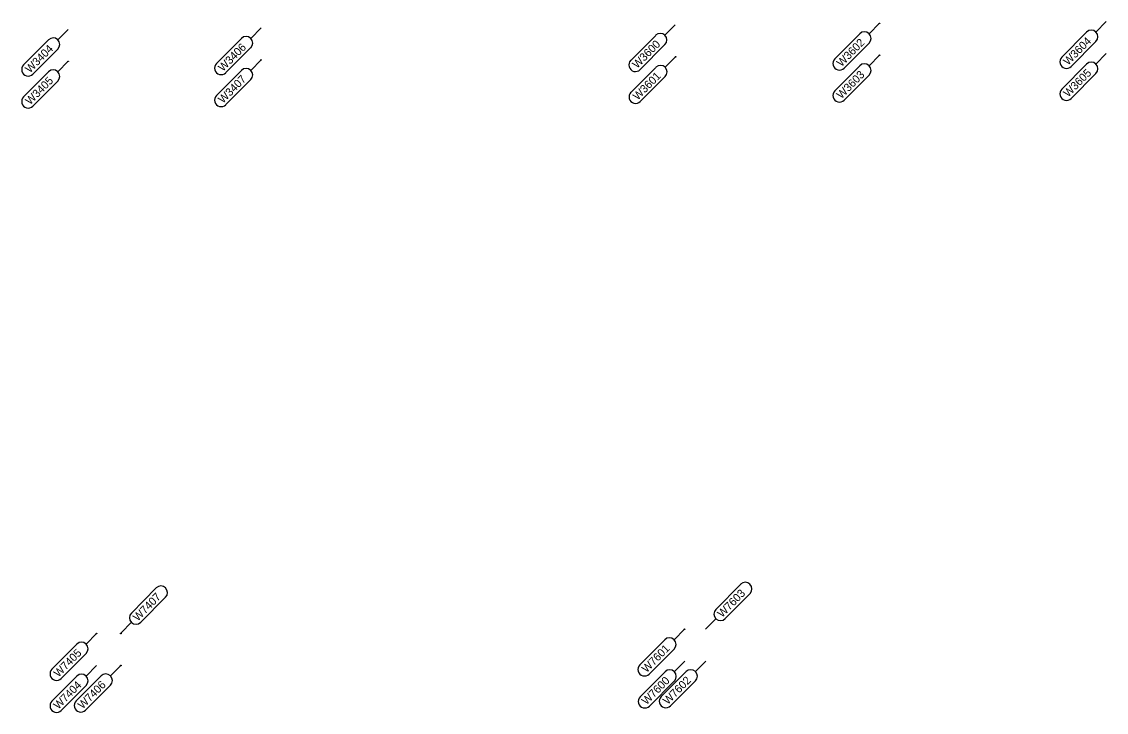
# Model space of a CAD drawing. Extents: x 12479652 to 12487250, y 9842710 to 9846560.
# Drawn here: x 12486116.6 to 12486286, y 9842763.4 to 9842871.3 of the extents above; entities that cross this region are included whole.
import ezdxf

# ---------------------------------------------------------------- set-up
doc = ezdxf.new("R2010")
doc.units = 0
doc.layers.add('_CIVIL_CONSTRUCTION', color=7, linetype='Continuous')
doc.layers.add('TextAlignmentLrg', color=7, linetype='Continuous')

msp = doc.modelspace()

# ---------------------------------------------------------------- linework, layer by layer
at = {"layer": '_CIVIL_CONSTRUCTION'}
for p, q in [((12486123.84, 9842870.13), (12486122.22, 9842868.5)), ((12486153.98, 9842870.35), (12486152.36, 9842868.72)), ((12486218.7, 9842870.83), (12486217.08, 9842869.2)), ((12486250.59, 9842871.07), (12486248.97, 9842869.43)), ((12486279.07, 9842865.78), (12486282.96, 9842869.69)), ((12486286.03, 9842871.33), (12486284.41, 9842869.7)), ((12486116.88, 9842864.58), (12486120.77, 9842868.49)), ((12486147.02, 9842864.8), (12486150.91, 9842868.72)), ((12486211.74, 9842865.28), (12486215.63, 9842869.19)), ((12486243.63, 9842865.52), (12486247.52, 9842869.43)), ((12486248.97, 9842867.98), (12486245.08, 9842864.07)), ((12486284.42, 9842868.25), (12486280.53, 9842864.33)), ((12486122.22, 9842867.05), (12486118.34, 9842863.13)), ((12486152.37, 9842867.27), (12486148.48, 9842863.36)), ((12486217.08, 9842867.75), (12486213.19, 9842863.84)), ((12486286.03, 9842866.33), (12486284.41, 9842864.7)), ((12486123.84, 9842865.13), (12486122.22, 9842863.5)), ((12486153.98, 9842865.35), (12486152.36, 9842863.72)), ((12486218.73, 9842865.83), (12486217.11, 9842864.2)), ((12486250.59, 9842866.07), (12486248.97, 9842864.43)), ((12486279.07, 9842860.78), (12486282.96, 9842864.69)), ((12486116.88, 9842859.58), (12486120.77, 9842863.49)), ((12486147.02, 9842859.8), (12486150.91, 9842863.72)), ((12486211.77, 9842860.28), (12486215.66, 9842864.19)), ((12486243.63, 9842860.52), (12486247.52, 9842864.43)), ((12486248.97, 9842862.98), (12486245.08, 9842859.07)), ((12486284.42, 9842863.25), (12486280.53, 9842859.33)), ((12486122.22, 9842862.05), (12486118.34, 9842858.13)), ((12486152.37, 9842862.27), (12486148.48, 9842858.36)), ((12486217.12, 9842862.75), (12486213.23, 9842858.84)), ((12486228.91, 9842783.38), (12486225.03, 9842779.45)), ((12486137.6, 9842782.8), (12486133.72, 9842778.88)), ((12486226.49, 9842778.01), (12486230.37, 9842781.94)), ((12486135.18, 9842777.43), (12486139.06, 9842781.36)), ((12486132.12, 9842775.79), (12486133.73, 9842777.43)), ((12486223.42, 9842776.36), (12486225.04, 9842778)), ((12486128.27, 9842775.66), (12486126.65, 9842774.03)), ((12486220.13, 9842776.34), (12486218.51, 9842774.71)), ((12486121.31, 9842770.11), (12486125.2, 9842774.02)), ((12486213.16, 9842770.79), (12486217.05, 9842774.7)), ((12486218.51, 9842773.26), (12486214.62, 9842769.34)), ((12486126.65, 9842772.58), (12486122.76, 9842768.66)), ((12486223.46, 9842771.36), (12486221.84, 9842769.73)), ((12486128.27, 9842770.66), (12486126.65, 9842769.03)), ((12486132.07, 9842770.69), (12486130.45, 9842769.06)), ((12486213.2, 9842765.79), (12486217.09, 9842769.7)), ((12486216.5, 9842765.81), (12486220.39, 9842769.73)), ((12486220.16, 9842771.34), (12486218.54, 9842769.71)), ((12486121.31, 9842765.11), (12486125.2, 9842769.02)), ((12486125.11, 9842765.14), (12486128.99, 9842769.05)), ((12486218.55, 9842768.26), (12486214.66, 9842764.34)), ((12486221.84, 9842768.28), (12486217.95, 9842764.37)), ((12486126.65, 9842767.58), (12486122.76, 9842763.66)), ((12486130.45, 9842767.61), (12486126.56, 9842763.69))]:
    msp.add_line(p, q, dxfattribs=at)
for centre, start, end in [((12486248.25, 9842868.71), 315.1702, 135.1702), ((12486283.69, 9842868.97), 315.1702, 135.1702), ((12486121.5, 9842867.77), 315.1702, 135.1702), ((12486151.64, 9842867.99), 315.1702, 135.1702), ((12486216.35, 9842868.47), 315.1702, 135.1702), ((12486117.61, 9842863.86), 135.1702, 315.1702), ((12486147.75, 9842864.08), 135.1702, 315.1702), ((12486212.46, 9842864.56), 135.1702, 315.1702), ((12486244.36, 9842864.79), 135.1702, 315.1702), ((12486248.25, 9842863.71), 315.1702, 135.1702), ((12486279.8, 9842865.06), 135.1702, 315.1702), ((12486283.69, 9842863.97), 315.1702, 135.1702), ((12486121.5, 9842862.77), 315.1702, 135.1702), ((12486151.64, 9842862.99), 315.1702, 135.1702), ((12486216.39, 9842863.47), 315.1702, 135.1702), ((12486117.61, 9842858.86), 135.1702, 315.1702), ((12486147.75, 9842859.08), 135.1702, 315.1702), ((12486212.5, 9842859.56), 135.1702, 315.1702), ((12486244.36, 9842859.79), 135.1702, 315.1702), ((12486279.8, 9842860.06), 135.1702, 315.1702), ((12486229.64, 9842782.66), 315.3788, 135.3788), ((12486138.33, 9842782.08), 315.3788, 135.3788), ((12486134.45, 9842778.16), 135.3788, 315.3788), ((12486225.76, 9842778.73), 135.3788, 315.3788), ((12486217.78, 9842773.98), 315.1702, 135.1702), ((12486125.93, 9842773.3), 315.1702, 135.1702), ((12486122.04, 9842769.39), 135.1702, 315.1702), ((12486213.89, 9842770.07), 135.1702, 315.1702), ((12486217.82, 9842768.98), 315.1702, 135.1702), ((12486221.12, 9842769), 315.1702, 135.1702), ((12486125.93, 9842768.3), 315.1702, 135.1702), ((12486129.72, 9842768.33), 315.1702, 135.1702), ((12486122.04, 9842764.39), 135.1702, 315.1702), ((12486125.83, 9842764.42), 135.1702, 315.1702), ((12486213.93, 9842765.07), 135.1702, 315.1702), ((12486217.23, 9842765.09), 135.1702, 315.1702)]:
    msp.add_arc(centre, 1.03, start, end, dxfattribs=at)
at = {"layer": 'TextAlignmentLrg'}
for centre in [(12486250.59, 9842871.07), (12486123.84, 9842865.13), (12486153.98, 9842865.35), (12486218.74, 9842865.83), (12486250.59, 9842866.07), (12486128.27, 9842775.66), (12486132.07, 9842775.69), (12486220.13, 9842776.34), (12486132.07, 9842770.69)]:
    msp.add_circle(centre, 0.05, dxfattribs=at)

# ---------------------------------------------------------------- texts
at = {"layer": '_CIVIL_CONSTRUCTION'}
for s, rotation, p in [('W3406', 45.1702, (12486148.02, 9842863.45)), ('W3600', 45.1702, (12486212.73, 9842863.93)), ('W3602', 45.1702, (12486244.65, 9842864.19)), ('W3604', 45.1702, (12486280.06, 9842864.42)), ('W3404', 45.1702, (12486117.87, 9842863.22)), ('W3407', 45.1702, (12486148.03, 9842858.46)), ('W3601', 45.1702, (12486212.81, 9842858.97)), ('W3603', 45.1702, (12486244.64, 9842859.17)), ('W3605', 45.1702, (12486280.08, 9842859.44)), ('W3405', 45.1702, (12486117.89, 9842858.24)), ('W7407', 45.3788, (12486134.72, 9842777.52)), ('W7603', 45.3788, (12486226.02, 9842778.09)), ('W7405', 45.1702, (12486122.32, 9842768.77)), ('W7601', 45.1702, (12486214.2, 9842769.47)), ('W7404', 45.1702, (12486122.3, 9842763.75)), ('W7406', 45.1702, (12486126.1, 9842763.79)), ('W7600', 45.1702, (12486214.2, 9842764.44)), ('W7602', 45.1702, (12486217.52, 9842764.48))]:
    msp.add_text(s, height=1.25, rotation=rotation, dxfattribs=at).set_placement(p)

doc.saveas('drawing.dxf')
